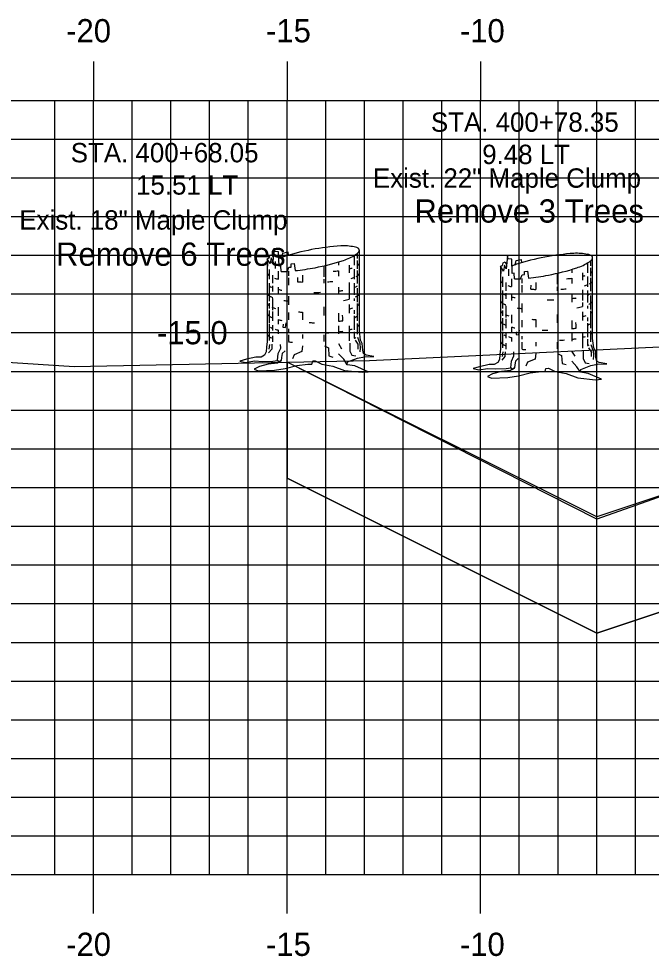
# Model space of a CAD drawing. Extents: x -161 to 764, y 111 to 210.
# Drawn here: x 388.66 to 405, y 174.14 to 198.36 of the extents above; entities that cross this region are included whole.
import ezdxf

# ---------------------------------------------------------------- set-up
doc = ezdxf.new("R2010")
doc.units = 0
for name, color, linetype in [('D_Slope_Cut', 7, 'Continuous'), ('D_Text_Monospaced', 7, 'Continuous'), ('D_Text_Standard', 7, 'Continuous'), ('H_V ANNOTATION', 7, 'Continuous'), ('MAJOR', 7, 'Continuous'), ('MINOR', 7, 'Continuous'), ('PATTERNING', 7, 'Continuous'), ('S_Roadway_Centerline', 7, 'Continuous'), ('S_Trees_Decid_Pay', 7, 'Continuous')]:
    doc.layers.add(name, color=color, linetype=linetype)

msp = doc.modelspace()

# ---------------------------------------------------------------- linework, layer by layer
at = {"layer": 'D_Slope_Cut'}
for p, q in [((395.597, 189.484), (395.592, 186.488)), ((403.591, 185.487), (395.597, 189.484)), ((406.591, 186.487), (403.591, 185.487))]:
    msp.add_line(p, q, dxfattribs=at)
msp.add_lwpolyline([(406.591, 183.487), (403.591, 182.487), (395.592, 186.488)], dxfattribs=at)
at = {"layer": 'MAJOR'}
for p, q in [((390.591, 197.249), (390.591, 196.247)), ((395.591, 197.249), (395.591, 196.247)), ((400.591, 197.249), (400.591, 196.247)), ((340.591, 196.247), (480.591, 196.247)), ((340.591, 196.247), (480.591, 196.247)), ((390.591, 176.247), (390.591, 196.247)), ((395.591, 176.247), (395.591, 196.247)), ((400.591, 176.247), (400.591, 196.247)), ((340.591, 191.247), (480.591, 191.247)), ((340.591, 186.247), (480.591, 186.247)), ((340.591, 181.247), (480.591, 181.247)), ((340.591, 176.247), (480.591, 176.247)), ((340.591, 176.247), (480.591, 176.247)), ((390.591, 175.245), (390.591, 176.247)), ((395.591, 175.245), (395.591, 176.247)), ((400.591, 175.245), (400.591, 176.247))]:
    msp.add_line(p, q, dxfattribs=at)
at = {"layer": 'MINOR'}
for p, q in [((389.591, 176.247), (389.591, 196.247)), ((391.591, 176.247), (391.591, 196.247)), ((392.591, 176.247), (392.591, 196.247)), ((393.591, 176.247), (393.591, 196.247)), ((394.591, 176.247), (394.591, 196.247)), ((396.591, 176.247), (396.591, 196.247)), ((397.591, 176.247), (397.591, 196.247)), ((398.591, 176.247), (398.591, 196.247)), ((399.591, 176.247), (399.591, 196.247)), ((401.591, 176.247), (401.591, 196.247)), ((402.591, 176.247), (402.591, 196.247)), ((403.591, 176.247), (403.591, 196.247)), ((404.591, 176.247), (404.591, 196.247)), ((340.591, 195.247), (480.591, 195.247)), ((340.591, 194.247), (480.591, 194.247)), ((340.591, 193.247), (480.591, 193.247)), ((340.591, 192.247), (480.591, 192.247)), ((340.591, 190.247), (480.591, 190.247)), ((340.591, 189.247), (480.591, 189.247)), ((340.591, 188.247), (480.591, 188.247)), ((340.591, 187.247), (480.591, 187.247)), ((340.591, 185.247), (480.591, 185.247)), ((340.591, 184.247), (480.591, 184.247)), ((340.591, 183.247), (480.591, 183.247)), ((340.591, 182.247), (480.591, 182.247)), ((340.591, 180.247), (480.591, 180.247)), ((340.591, 179.247), (480.591, 179.247)), ((340.591, 178.247), (480.591, 178.247)), ((340.591, 177.247), (480.591, 177.247))]:
    msp.add_line(p, q, dxfattribs=at)
at = {"layer": 'PATTERNING'}
msp.add_lwpolyline([(395.597, 189.484), (395.592, 186.488), (403.591, 182.487), (406.591, 183.487), (406.591, 186.487), (403.592, 185.431)], close=True, dxfattribs=at)
at = {"layer": 'S_Roadway_Centerline'}
msp.add_lwpolyline([(340.591, 183.558), (346.27, 184.146), (348.315, 184.806), (354.074, 186.337), (357.168, 187.075), (364.507, 188.564), (366.124, 189.037), (373.039, 189.084), (380.424, 189.717), (384.106, 189.757), (390.092, 189.37), (397.718, 189.529), (407.599, 189.997), (414.618, 189.716), (422.879, 189.785), (430.793, 190.018)], dxfattribs=at)
at = {"layer": 'S_Trees_Decid_Pay'}
for p, q in [((395.282, 192.081), (395.282, 191.907)), ((396.921, 192.073), (396.921, 191.987)), ((397.326, 192.24), (397.326, 191.987)), ((397.406, 192.284), (397.406, 192.164)), ((397.406, 192.112), (397.406, 191.898)), ((403.353, 192.048), (403.353, 191.795)), ((403.433, 192.092), (403.433, 191.972)), ((395.132, 191.881), (395.132, 191.626)), ((395.366, 191.832), (395.366, 191.628)), ((395.628, 191.834), (395.628, 191.715)), ((396.538, 191.972), (396.538, 191.692)), ((396.921, 191.845), (396.921, 191.706)), ((397.194, 191.987), (397.194, 191.795)), ((397.326, 191.89), (397.326, 191.626)), ((397.406, 191.853), (397.406, 191.515)), ((401.308, 191.889), (401.308, 191.715)), ((402.948, 191.881), (402.948, 191.795)), ((403.433, 191.92), (403.433, 191.706)), ((395.218, 191.735), (395.218, 191.523)), ((395.628, 191.663), (395.628, 191.478)), ((395.866, 191.563), (395.871, 191.67)), ((395.992, 191.735), (395.992, 191.555)), ((396.538, 191.626), (396.538, 191.523)), ((401.158, 191.689), (401.158, 191.434)), ((401.393, 191.64), (401.393, 191.436)), ((401.654, 191.642), (401.654, 191.523)), ((402.565, 191.78), (402.565, 191.5)), ((402.948, 191.653), (402.948, 191.514)), ((403.22, 191.795), (403.22, 191.603)), ((403.353, 191.698), (403.353, 191.434)), ((403.433, 191.661), (403.433, 191.323)), ((395.132, 191.529), (395.132, 191.06)), ((395.218, 191.458), (395.218, 191.309)), ((395.366, 191.42), (395.366, 191.266)), ((396.921, 191.42), (396.921, 191.229)), ((397.194, 191.544), (397.194, 191.266)), ((397.326, 191.529), (397.326, 191.221)), ((397.406, 191.398), (397.406, 191.037)), ((401.158, 191.337), (401.158, 190.868)), ((401.244, 191.543), (401.244, 191.331)), ((401.654, 191.471), (401.654, 191.286)), ((401.892, 191.371), (401.897, 191.478)), ((402.019, 191.543), (402.019, 191.363)), ((402.565, 191.434), (402.565, 191.331)), ((403.22, 191.352), (403.22, 191.074)), ((403.353, 191.337), (403.353, 191.029)), ((395.218, 191.132), (395.218, 190.832)), ((395.628, 191.192), (395.628, 190.964)), ((397.194, 191.221), (397.194, 191.112)), ((397.326, 191.132), (397.326, 191.066)), ((401.244, 191.266), (401.244, 191.117)), ((401.393, 191.228), (401.393, 191.074)), ((402.948, 191.228), (402.948, 191.037)), ((403.433, 191.206), (403.433, 190.845)), ((395.132, 191.009), (395.132, 190.875)), ((395.366, 190.903), (395.366, 190.683)), ((396.538, 190.912), (396.538, 190.691)), ((397.194, 190.977), (397.194, 190.749)), ((397.406, 191), (397.406, 190.552)), ((401.244, 190.94), (401.244, 190.64)), ((401.654, 191), (401.654, 190.772)), ((403.22, 191.029), (403.22, 190.92)), ((403.353, 190.94), (403.353, 190.874)), ((395.132, 190.817), (395.132, 190.492)), ((395.218, 190.794), (395.218, 190.552)), ((395.628, 190.765), (395.628, 190.58)), ((395.992, 190.777), (395.992, 190.58)), ((396.921, 190.749), (396.921, 190.541)), ((397.326, 190.832), (397.326, 190.735)), ((397.326, 190.683), (397.326, 190.323)), ((401.158, 190.817), (401.158, 190.683)), ((401.158, 190.625), (401.158, 190.3)), ((401.244, 190.602), (401.244, 190.36)), ((401.393, 190.711), (401.393, 190.491)), ((402.565, 190.72), (402.565, 190.499)), ((403.22, 190.785), (403.22, 190.557)), ((403.353, 190.64), (403.353, 190.543)), ((403.433, 190.808), (403.433, 190.36)), ((395.132, 190.463), (395.132, 190.043)), ((395.218, 190.441), (395.218, 190.3)), ((395.366, 190.584), (395.366, 190.463)), ((396.921, 190.42), (396.921, 190.22)), ((397.194, 190.42), (397.194, 190.036)), ((397.406, 190.486), (397.406, 190.204)), ((401.393, 190.392), (401.393, 190.271)), ((401.654, 190.573), (401.654, 190.388)), ((402.019, 190.585), (402.019, 190.388)), ((402.948, 190.557), (402.948, 190.349)), ((403.353, 190.491), (403.353, 190.131)), ((395.218, 190.168), (395.218, 190.012)), ((395.366, 190.312), (395.366, 190.214)), ((395.628, 190.345), (395.628, 190.269)), ((395.628, 190.191), (395.628, 190.018)), ((395.992, 190.197), (395.992, 190.094)), ((396.538, 190.191), (396.538, 190.018)), ((397.326, 190.271), (397.326, 190.105)), ((401.158, 190.271), (401.158, 189.851)), ((401.244, 190.249), (401.244, 190.108)), ((401.393, 190.12), (401.393, 190.022)), ((401.654, 190.153), (401.654, 190.077)), ((402.948, 190.228), (402.948, 190.028)), ((403.22, 190.228), (403.22, 189.844)), ((403.433, 190.294), (403.433, 190.012)), ((395.135, 189.94), (395.121, 189.823)), ((396.917, 189.963), (396.997, 189.831)), ((401.244, 189.976), (401.244, 189.82)), ((401.654, 189.999), (401.654, 189.826)), ((402.019, 190.005), (402.019, 189.902)), ((402.565, 189.999), (402.565, 189.826)), ((403.353, 190.079), (403.353, 189.913)), ((401.162, 189.748), (401.147, 189.631)), ((402.943, 189.771), (403.023, 189.639))]:
    msp.add_line(p, q, dxfattribs=at)
for points in [[(395.082, 192.155), (395.082, 190.018), (395.061, 189.876), (395.055, 189.75), (395.012, 189.664), (394.92, 189.615), (394.784, 189.615), (394.54, 189.559), (394.374, 189.51), (394.516, 189.479), (394.753, 189.516), (394.963, 189.504), (395.224, 189.51), (395.348, 189.528), (395.378, 189.485), (395.441, 189.528), (395.341, 189.46), (395.107, 189.435), (394.876, 189.374), (394.746, 189.303), (394.845, 189.26), (395.267, 189.279), (395.546, 189.323), (395.844, 189.399), (396.13, 189.435), (396.235, 189.435), (396.254, 189.516), (396.322, 189.522), (396.488, 189.435), (396.775, 189.38), (397.073, 189.273), (397.532, 189.223), (397.687, 189.236), (397.345, 189.386), (397.141, 189.417), (397.153, 189.491), (397.413, 189.59), (397.588, 189.621), (397.829, 189.633), (397.631, 189.67), (397.569, 189.707), (397.545, 189.794), (397.532, 189.963), (397.487, 190.049), (397.459, 190.29), (397.459, 192.376)], [(395.438, 191.828), (395.43, 191.972), (395.385, 191.964), (395.37, 192.339), (395.276, 192.347), (395.261, 192.427), (395.224, 192.09), (395.179, 192.184), (395.158, 192.03), (395.082, 192.155), (395.088, 191.966)], [(395.46, 192.194), (395.481, 192.302), (395.613, 192.332), (395.62, 192.244)], [(395.082, 192.155), (395.128, 192.178), (395.15, 192.244), (395.202, 192.267), (395.235, 192.192)], [(401.108, 191.963), (401.108, 189.826), (401.088, 189.684), (401.082, 189.558), (401.038, 189.472), (400.946, 189.423), (400.81, 189.423), (400.567, 189.367), (400.4, 189.318), (400.542, 189.287), (400.779, 189.324), (400.989, 189.312), (401.25, 189.318), (401.374, 189.336), (401.405, 189.293), (401.467, 189.336), (401.368, 189.268), (401.133, 189.243), (400.903, 189.182), (400.773, 189.111), (400.872, 189.068), (401.294, 189.087), (401.572, 189.131), (401.87, 189.207), (402.157, 189.243), (402.261, 189.243), (402.28, 189.324), (402.348, 189.33), (402.515, 189.243), (402.801, 189.188), (403.099, 189.081), (403.559, 189.031), (403.713, 189.044), (403.371, 189.194), (403.168, 189.225), (403.179, 189.299), (403.439, 189.398), (403.615, 189.429), (403.855, 189.441), (403.657, 189.478), (403.595, 189.515), (403.571, 189.602), (403.559, 189.771), (403.513, 189.857), (403.485, 190.098), (403.485, 192.184)], [(401.464, 191.636), (401.456, 191.78), (401.411, 191.772), (401.397, 192.147), (401.302, 192.155), (401.288, 192.235), (401.25, 191.898), (401.205, 191.992), (401.185, 191.838), (401.108, 191.963), (401.114, 191.774)], [(401.108, 191.963), (401.154, 191.986), (401.176, 192.052), (401.228, 192.075), (401.262, 192)], [(401.487, 192.002), (401.508, 192.11), (401.639, 192.14), (401.647, 192.052)], [(395.599, 191.832), (395.636, 191.935), (395.702, 191.941), (395.702, 192.023), (395.776, 192.03), (395.801, 191.849)], [(401.626, 191.64), (401.662, 191.743), (401.728, 191.749), (401.728, 191.831), (401.802, 191.838), (401.827, 191.657)], [(397.035, 190.555), (397.034, 190.632), (397.026, 190.698)], [(395.49, 190.463), (395.481, 190.389), (395.555, 190.383), (395.57, 190.5)], [(403.061, 190.363), (403.06, 190.44), (403.052, 190.506)], [(397.408, 190.132), (397.469, 189.971), (397.483, 189.845), (397.475, 189.748)], [(401.516, 190.271), (401.508, 190.197), (401.582, 190.191), (401.596, 190.308)], [(395.202, 189.948), (395.195, 189.823), (395.113, 189.728)], [(395.348, 189.528), (395.366, 189.707), (395.428, 189.844), (395.421, 189.944)], [(395.99, 189.911), (395.973, 189.757), (395.776, 189.676), (395.731, 189.573)], [(396.556, 189.903), (396.659, 189.851), (396.673, 189.645), (396.776, 189.616)], [(397.211, 189.977), (397.211, 189.771), (397.269, 189.662), (397.366, 189.645)], [(397.351, 190.051), (397.423, 189.948), (397.423, 189.823)], [(403.435, 189.94), (403.495, 189.779), (403.509, 189.653), (403.501, 189.556)], [(395.539, 189.775), (395.465, 189.707), (395.446, 189.609), (395.441, 189.528)], [(397.141, 189.417), (397.055, 189.559), (396.923, 189.701)], [(401.228, 189.756), (401.221, 189.631), (401.139, 189.536)], [(401.374, 189.336), (401.393, 189.515), (401.454, 189.652), (401.448, 189.752)], [(402.017, 189.719), (402, 189.565), (401.802, 189.484), (401.757, 189.381)], [(402.582, 189.711), (402.685, 189.659), (402.7, 189.453), (402.803, 189.424)], [(403.237, 189.785), (403.237, 189.579), (403.295, 189.47), (403.392, 189.453)], [(403.378, 189.859), (403.449, 189.756), (403.449, 189.631)], [(401.565, 189.583), (401.491, 189.515), (401.473, 189.417), (401.467, 189.336)], [(403.168, 189.225), (403.081, 189.367), (402.949, 189.509)]]:
    msp.add_lwpolyline(points, dxfattribs=at)
for centre, radius, start, end in [((397.372, 186.374), 6.126, 100.7779, 107.8613), ((397.372, 186.374), 6.126, 93.6944, 100.7779), ((397.061, 191.19), 1.299, 78.2779, 93.6944), ((397.227, 191.993), 0.48, 69.9843, 78.2779), ((397.1, 192.664), 0.48, 303.2779, 311.5714), ((397.335, 192.29), 0.164, 55.7779, 69.9843), ((397.309, 192.428), 0.164, 311.5714, 325.7779), ((397.367, 192.337), 0.107, 45.9547, 55.7779), ((397.397, 192.367), 0.0645, 33.2779, 45.9547), ((397.356, 192.396), 0.107, 325.7779, 335.6011), ((397.405, 192.373), 0.0544, 22.46, 33.2779), ((397.395, 192.378), 0.0645, 335.6011, 348.2779), ((397.412, 192.376), 0.0467, 10.7779, 22.46), ((397.412, 192.376), 0.0467, 359.0957, 10.7779), ((397.405, 192.376), 0.0544, 348.2779, 359.0957), ((403.398, 186.182), 6.126, 93.6944, 100.7779), ((403.087, 190.998), 1.299, 78.2779, 93.6944), ((395.891, 190.968), 1.299, 107.8613, 113.3069), ((395.169, 197.943), 6.126, 280.7779, 287.8613), ((396.65, 193.349), 1.299, 287.8613, 303.2779), ((403.398, 186.182), 6.126, 100.7779, 107.8613), ((402.676, 193.157), 1.299, 287.8613, 303.2779), ((403.254, 191.801), 0.48, 69.9843, 78.2779), ((403.126, 192.472), 0.48, 303.2779, 311.5714), ((403.362, 192.098), 0.164, 55.7779, 69.9843), ((403.335, 192.236), 0.164, 311.5714, 325.7779), ((403.393, 192.145), 0.107, 45.9547, 55.7779), ((403.423, 192.175), 0.0645, 33.2779, 45.9547), ((403.382, 192.204), 0.107, 325.7779, 335.6011), ((403.432, 192.181), 0.0544, 22.46, 33.2779), ((403.421, 192.186), 0.0645, 335.6011, 348.2779), ((403.439, 192.184), 0.0467, 10.7779, 22.46), ((403.431, 192.184), 0.0544, 348.2779, 359.0957), ((403.439, 192.184), 0.0467, 359.0957, 10.7779), ((395.48, 193.126), 1.299, 268.1289, 273.6944), ((395.169, 197.943), 6.126, 273.6944, 274.0246), ((395.169, 197.943), 6.126, 275.9147, 280.7779), ((396.271, 197.726), 5.916, 274.9514, 276.3087), ((396.847, 193.138), 1.292, 285.5651, 289.0916), ((397.319, 192.119), 0.166, 301.67, 315), ((397.36, 192.078), 0.109, 315, 324.8263), ((397.395, 192.053), 0.0657, 324.8263, 337.5), ((397.405, 192.049), 0.0554, 337.5, 348.3185), ((401.918, 190.776), 1.299, 107.8613, 113.3069), ((401.196, 197.751), 6.126, 280.7779, 287.8613), ((403.346, 191.927), 0.166, 301.67, 315), ((403.386, 191.886), 0.109, 315, 324.8263), ((403.422, 191.861), 0.0657, 324.8263, 337.5), ((403.431, 191.857), 0.0554, 337.5, 348.3185), ((395.129, 191.787), 0.0476, 180, 191.6815), ((395.137, 191.788), 0.0554, 191.6815, 202.5), ((395.147, 191.792), 0.0657, 202.5, 215.1737), ((395.182, 191.817), 0.109, 215.1737, 225), ((395.223, 191.858), 0.166, 225, 239.1924), ((395.695, 192.877), 1.292, 250.6119, 255.2856), ((396.27, 197.465), 5.916, 266.0776, 267.3043), ((396.27, 197.465), 5.916, 273.5382, 274.8924), ((396.846, 192.877), 1.292, 288.0829, 292.5), ((397.155, 192.131), 0.484, 297.4162, 300.8076), ((397.318, 191.858), 0.166, 300.8076, 315), ((397.359, 191.817), 0.109, 315, 324.8263), ((397.394, 191.792), 0.0657, 324.8263, 337.5), ((397.404, 191.788), 0.0554, 337.5, 348.3185), ((401.156, 191.595), 0.0476, 180, 191.6815), ((401.164, 191.596), 0.0554, 191.6815, 202.5), ((401.173, 191.6), 0.0657, 202.5, 215.1737), ((401.208, 191.625), 0.109, 215.1737, 225), ((401.507, 192.934), 1.299, 268.1289, 273.6944), ((401.196, 197.751), 6.126, 273.6944, 274.0246), ((401.196, 197.751), 6.126, 275.9147, 280.7779), ((402.298, 197.534), 5.916, 274.9514, 276.3087), ((402.874, 192.946), 1.292, 285.5651, 289.0916), ((403.385, 191.625), 0.109, 315, 324.8263), ((403.421, 191.6), 0.0657, 324.8263, 337.5), ((403.43, 191.596), 0.0554, 337.5, 348.3185), ((395.223, 191.594), 0.166, 237.0378, 239.1924), ((395.385, 191.867), 0.484, 239.1924, 247.5), ((395.695, 192.614), 1.292, 247.5, 248.3537), ((395.695, 192.614), 1.292, 255.2856, 259.2632), ((396.27, 197.202), 5.916, 276.3183, 277.1546), ((396.846, 192.614), 1.292, 277.1546, 278.3662), ((396.846, 192.614), 1.292, 291.8071, 292.5), ((397.155, 191.867), 0.484, 292.5, 300.8076), ((397.318, 191.594), 0.166, 300.8076, 301.6001), ((401.249, 191.666), 0.166, 225, 239.1924), ((401.721, 192.685), 1.292, 250.6119, 255.2856), ((402.297, 197.273), 5.916, 266.0776, 267.3043), ((402.297, 197.273), 5.916, 273.5382, 274.8924), ((402.873, 192.685), 1.292, 288.0829, 292.5), ((403.182, 191.939), 0.484, 297.4162, 300.8076), ((403.345, 191.666), 0.166, 300.8076, 315), ((395.129, 191.266), 0.0476, 180, 191.6815), ((395.137, 191.268), 0.0554, 191.6815, 202.5), ((395.147, 191.271), 0.0657, 202.5, 215.1737), ((395.182, 191.296), 0.109, 215.1737, 225), ((395.223, 191.337), 0.166, 225, 239.1924), ((395.385, 191.61), 0.484, 239.1924, 245.7724), ((395.695, 192.356), 1.292, 247.5, 248.4842), ((395.695, 192.356), 1.292, 261.8726, 262.8454), ((396.27, 197.202), 5.916, 270.1162, 271.7708), ((396.846, 192.356), 1.292, 279.2565, 285.6105), ((397.155, 191.61), 0.484, 294.6372, 300.8076), ((397.318, 191.337), 0.166, 300.8076, 315), ((397.359, 191.296), 0.109, 315, 324.8263), ((397.394, 191.271), 0.0657, 324.8263, 337.5), ((397.404, 191.268), 0.0554, 337.5, 348.3185), ((401.249, 191.402), 0.166, 237.0378, 239.1924), ((401.412, 191.675), 0.484, 239.1924, 247.5), ((401.721, 192.422), 1.292, 247.5, 248.3537), ((401.721, 192.422), 1.292, 255.2856, 259.2632), ((402.297, 197.01), 5.916, 270.1162, 271.7708), ((402.297, 197.01), 5.916, 276.3183, 277.1546), ((402.873, 192.422), 1.292, 277.1546, 278.3662), ((402.873, 192.422), 1.292, 291.8071, 292.5), ((403.182, 191.675), 0.484, 292.5, 300.8076), ((403.345, 191.402), 0.166, 300.8076, 301.6001), ((395.129, 191.009), 0.0476, 180, 191.6815), ((395.137, 191.01), 0.0554, 191.6815, 202.5), ((395.147, 191.014), 0.0657, 202.5, 215.1737), ((395.182, 191.039), 0.109, 215.1737, 225), ((395.223, 191.08), 0.166, 225, 239.1924), ((395.695, 192.099), 1.292, 247.5, 251.799), ((396.27, 196.944), 5.916, 262.8454, 263.7595), ((396.846, 192.099), 1.292, 285.6105, 290.1001), ((397.318, 191.08), 0.166, 302.0694, 315), ((397.359, 191.039), 0.109, 315, 324.8263), ((397.394, 191.014), 0.0657, 324.8263, 337.5), ((397.404, 191.01), 0.0554, 337.5, 348.3185), ((401.156, 191.074), 0.0476, 180, 191.6815), ((401.164, 191.076), 0.0554, 191.6815, 202.5), ((401.173, 191.079), 0.0657, 202.5, 215.1737), ((401.208, 191.104), 0.109, 215.1737, 225), ((401.249, 191.145), 0.166, 225, 239.1924), ((401.412, 191.418), 0.484, 239.1924, 245.7724), ((401.721, 192.164), 1.292, 247.5, 248.4842), ((401.721, 192.164), 1.292, 261.8726, 262.8454), ((402.297, 196.752), 5.916, 262.8454, 263.7595), ((402.873, 192.164), 1.292, 279.2565, 285.6105), ((403.182, 191.418), 0.484, 294.6372, 300.8076), ((403.345, 191.145), 0.166, 300.8076, 315), ((403.385, 191.104), 0.109, 315, 324.8263), ((403.421, 191.079), 0.0657, 324.8263, 337.5), ((403.43, 191.076), 0.0554, 337.5, 348.3185), ((395.129, 190.743), 0.0476, 180, 191.6815), ((395.137, 190.745), 0.0554, 191.6815, 202.5), ((395.147, 190.748), 0.0657, 202.5, 215.1737), ((395.182, 190.773), 0.109, 215.1737, 225), ((395.223, 190.814), 0.166, 225, 239.1924), ((395.385, 191.087), 0.484, 239.1924, 247.5), ((395.695, 191.833), 1.292, 247.5, 248.3537), ((396.27, 196.687), 5.916, 266.2721, 267.3043), ((397.155, 191.087), 0.484, 292.5, 300.8076), ((397.318, 190.814), 0.166, 300.8076, 302.0694), ((397.404, 190.745), 0.0554, 337.5, 348.3185), ((401.156, 190.817), 0.0476, 180, 191.6815), ((401.164, 190.818), 0.0554, 191.6815, 202.5), ((401.173, 190.822), 0.0657, 202.5, 215.1737), ((401.208, 190.847), 0.109, 215.1737, 225), ((401.249, 190.888), 0.166, 225, 239.1924), ((401.721, 191.907), 1.292, 247.5, 251.799), ((402.873, 191.907), 1.292, 285.6105, 290.1001), ((403.345, 190.888), 0.166, 302.0694, 315), ((403.385, 190.847), 0.109, 315, 324.8263), ((403.421, 190.822), 0.0657, 324.8263, 337.5), ((403.43, 190.818), 0.0554, 337.5, 348.3185), ((395.385, 190.815), 0.484, 242.734, 247.5), ((395.695, 191.833), 1.292, 255.2856, 259.2463), ((396.27, 196.421), 5.916, 268.9206, 270), ((396.27, 196.421), 5.916, 270, 270.2757), ((396.27, 196.421), 5.916, 276.3183, 277.1546), ((396.846, 191.833), 1.292, 277.1546, 278.3795), ((397.318, 190.542), 0.166, 302.0694, 315), ((397.359, 190.502), 0.109, 315, 324.8263), ((397.394, 190.477), 0.0657, 324.8263, 337.5), ((397.404, 190.473), 0.0554, 337.5, 348.3185), ((401.156, 190.551), 0.0476, 180, 191.6815), ((401.164, 190.553), 0.0554, 191.6815, 202.5), ((401.173, 190.556), 0.0657, 202.5, 215.1737), ((401.208, 190.581), 0.109, 215.1737, 225), ((401.249, 190.622), 0.166, 225, 239.1924), ((401.412, 190.895), 0.484, 239.1924, 247.5), ((401.721, 191.641), 1.292, 247.5, 248.3537), ((401.721, 191.641), 1.292, 255.2856, 259.2463), ((402.297, 196.495), 5.916, 266.2721, 267.3043), ((402.297, 196.229), 5.916, 276.3183, 277.1546), ((402.873, 191.641), 1.292, 277.1546, 278.3795), ((403.182, 190.895), 0.484, 292.5, 300.8076), ((403.345, 190.622), 0.166, 300.8076, 302.0694), ((403.43, 190.553), 0.0554, 337.5, 348.3185), ((395.129, 190.214), 0.0476, 180, 191.6815), ((395.137, 190.215), 0.0554, 191.6815, 202.5), ((395.147, 190.219), 0.0657, 202.5, 215.1737), ((395.182, 190.244), 0.109, 215.1737, 225), ((395.223, 190.285), 0.166, 225, 239.1924), ((395.385, 190.558), 0.484, 239.1924, 247.5), ((395.695, 191.304), 1.292, 247.5, 248.3537), ((395.695, 191.561), 1.292, 251.3664, 255.2856), ((396.27, 196.149), 5.916, 273.2637, 274.461), ((396.27, 196.149), 5.916, 276.3183, 277.1546), ((396.846, 191.561), 1.292, 277.1546, 278.3662), ((396.846, 191.561), 1.292, 285.6105, 289.1534), ((396.856, 191.308), 1.292, 291.3696, 292.0604), ((397.155, 190.558), 0.484, 292.5, 296.5499), ((401.412, 190.623), 0.484, 242.734, 247.5), ((401.721, 191.369), 1.292, 251.3664, 255.2856), ((402.297, 196.229), 5.916, 268.9206, 270), ((402.297, 196.229), 5.916, 270, 270.2757), ((402.873, 191.369), 1.292, 285.6105, 289.1534), ((403.345, 190.35), 0.166, 302.0694, 315), ((403.385, 190.31), 0.109, 315, 324.8263), ((403.421, 190.285), 0.0657, 324.8263, 337.5), ((403.43, 190.281), 0.0554, 337.5, 348.3185), ((396.27, 195.892), 5.916, 263.7831, 264.7655), ((401.156, 190.022), 0.0476, 180, 191.6815), ((401.164, 190.023), 0.0554, 191.6815, 202.5), ((401.173, 190.027), 0.0657, 202.5, 215.1737), ((401.208, 190.052), 0.109, 215.1737, 225), ((401.249, 190.093), 0.166, 225, 239.1924), ((401.412, 190.366), 0.484, 239.1924, 247.5), ((401.721, 191.112), 1.292, 247.5, 248.3537), ((402.297, 195.957), 5.916, 273.2637, 274.461), ((402.297, 195.957), 5.916, 276.3183, 277.1546), ((402.873, 191.369), 1.292, 277.1546, 278.3662), ((402.882, 191.116), 1.292, 291.3696, 292.0604), ((403.182, 190.366), 0.484, 292.5, 296.5499), ((402.297, 195.7), 5.916, 263.7831, 264.7655)]:
    msp.add_arc(centre, radius, start, end, dxfattribs=at)

# ---------------------------------------------------------------- texts
at = {"layer": 'D_Text_Monospaced'}
for s, height, p in [('STA. 400+78.35', 0.49998, (399.308, 195.436)), ('STA. 400+68.05', 0.49998, (390.004, 194.647)), ('9.48 LT', 0.5, (400.634, 194.602)), ('Exist. 22" Maple Clump', 0.49998, (397.81, 193.991)), ('15.51 LT', 0.5, (391.691, 193.813)), ('Exist. 18" Maple Clump', 0.49998, (388.675, 192.909))]:
    msp.add_text(s, height=height, dxfattribs=at).set_placement(p)
at = {"layer": 'D_Text_Standard'}
for s, p in [('Remove 3 Trees', (398.881, 193.09)), ('Remove 6 Trees', (389.624, 191.975)), ('-15.0', (392.229, 189.947))]:
    msp.add_text(s, height=0.6, dxfattribs=at).set_placement(p)
at = {"layer": 'H_V ANNOTATION'}
for s, p in [('-20', (389.885, 197.747)), ('-15', (395.048, 197.747)), ('-10', (400.056, 197.747)), ('-20', (389.885, 174.147)), ('-15', (395.048, 174.147)), ('-10', (400.056, 174.147))]:
    msp.add_text(s, height=0.6, rotation=360, dxfattribs=at).set_placement(p)

doc.saveas('drawing.dxf')
